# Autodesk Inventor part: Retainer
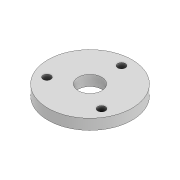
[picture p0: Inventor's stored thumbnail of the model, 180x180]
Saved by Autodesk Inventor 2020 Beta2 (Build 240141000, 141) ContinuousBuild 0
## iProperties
Created: 2019-03
Part Number: Retainer
Material: Generic
Document SubType Name: Modeling
Designer: LENOVO-CADCIM
Density: 1 g/cm^3
Appearance: Default
Author: LENOVO-CADCIM
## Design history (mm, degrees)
sketch "Sketch1" dims "d1" = 150
  geometry: C1 r 100 at (0, 0); 3 further points
  constraints: 2 coincident, 1 centre point, 1 vertical alignment, 2 other
  dimensions: "d0" = 200 diameter of C1
extrude "Extrusion1" new body sketch "Sketch1" stored distance "d2" = 25; taper "d3" = 0 deg
sketch "Sketch2" dims "d4" = 150
  geometry: 3 further points
  constraints: 1 coincident, 1 vertical alignment, 2 other
hole "Hole1" sketch "Sketch2" at (0, 75) diameter "d5" = 18.376; stored, may be unused: countersink angle "d9" = 90 deg, drill point angle "d11" = 118 deg; dims "d6" = 40, "d7" = 4.4, "d8" = 2, "d10" = 47.3
pattern_circular "Circular Pattern1" dims angle "d13" = 360 deg
sketch "Sketch3"
  geometry: C1 r 28 at (0, 0); 1 further point
  constraints: 1 centre point, 1 coincident
  dimensions: "d15" = 56 diameter of C1
extrude "Extrusion2" cut sketch "Sketch3" distance "d16" = 25; taper "d17" = 0 deg
body "Solid1"
